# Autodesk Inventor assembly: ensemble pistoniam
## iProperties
Shininess: 64.0
Length Units: 11269
Angle Units: 11279
Time Units: 11290
Mass Units: 11283
Length Display Precision: 3
Angle Display Precision: 2
Compacted: True
Created: 2005-04
Part Number: ensemble pistoniam
Document SubType Name: Assembly
Designer: thchene
Density: 0.0
Volumn: 0.0
Area: 0.0
PropertySet Name: Model Information
Control State: 0
Master: False
Checked Out: False
Author: thchene
